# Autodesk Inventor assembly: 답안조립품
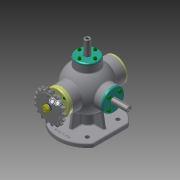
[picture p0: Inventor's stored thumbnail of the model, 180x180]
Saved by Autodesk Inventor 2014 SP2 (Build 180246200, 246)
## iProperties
Created: 2016-03
Part Number: 답안조립품
Document SubType Name: Assembly
Designer: apexhp001
Mass: 1992.22 g
Surface Area: 2215.45 cm^2
Volume: 827.087 cm^3
Density: 2.40872 g/cm^3
Author: apexhp001
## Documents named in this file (17)
- C:\Users\1sil_ho3333\Desktop\360308V1011\답안조립품.iam
- C:\Users\1sil_ho3333\Desktop\360308V1011\본체.ipt
- C:\Users\1sil_ho3333\Desktop\360308V1011\너트-M8x1.ipt
- C:\Users\1sil_ho3333\Desktop\360308V1011\뒤커버.ipt
- C:\Users\1sil_ho3333\Desktop\360308V1011\베어링- 6202.ipt
- C:\Users\1sil_ho3333\Desktop\360308V1011\본체커버.ipt
- C:\Users\1sil_ho3333\Desktop\360308V1011\볼트 M4x0.7.ipt
- C:\Users\1sil_ho3333\Desktop\360308V1011\스프로킷.ipt
- C:\Users\1sil_ho3333\Desktop\360308V1011\슬라이드 커버.ipt
- C:\Users\1sil_ho3333\Desktop\360308V1011\슬라이드.ipt
- C:\Users\1sil_ho3333\Desktop\360308V1011\앞커버.ipt
- C:\Users\1sil_ho3333\Desktop\360308V1011\오일실.ipt
- C:\Users\1sil_ho3333\Desktop\360308V1011\와셔 8x17.ipt
- C:\Users\1sil_ho3333\Desktop\360308V1011\축.ipt
- C:\Users\1sil_ho3333\Desktop\360308V1011\키 3 x 3 x 12.ipt
- C:\Users\1sil_ho3333\Desktop\360308V1011\스프링1.ipt
- C:\Users\1sil_ho3333\Desktop\360308V1011\스프링2.ipt
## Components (17 placed, 1 different names)
1. M4x0.7x12:5 — 각도:1
2. M4x0.7x12:1 — 각도:2
3. M4x0.7x12:6
4. M4x0.7x12:7
5. M4x0.7x12:8
6. M4x0.7x12:4 — 각도:3
7. M4x0.7x12:9
8. M4x0.7x12:10
9. M4x0.7x12:11
10. M4x0.7x12:3 — 각도:4
11. M4x0.7x12:12
12. M4x0.7x12:13
13. M4x0.7x12:14
14. M4x0.7x12:2 — 각도:5
15. M4x0.7x12:15
16. M4x0.7x12:16
17. M4x0.7x12:17
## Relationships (5: Angle 5)
- 각도:1 [Angle]: M4x0.7x12:5
- 각도:2 [Angle]: M4x0.7x12:1
- 각도:3 [Angle]: M4x0.7x12:4
- 각도:4 [Angle]: M4x0.7x12:3
- 각도:5 [Angle]: M4x0.7x12:2
